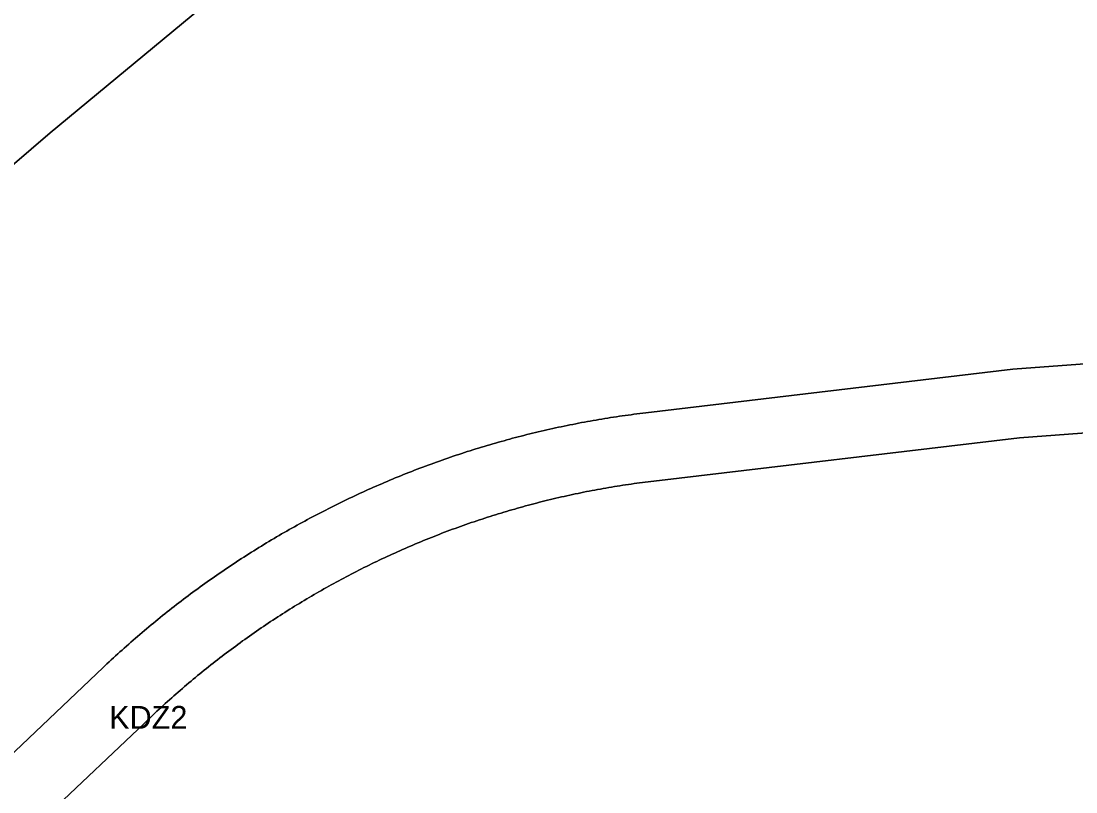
# Model space of a CAD drawing. Extents: x 7439486 to 7443435, y 5551288 to 5554556.
# Drawn here: x 7440134.7 to 7440595.5, y 5551897.3 to 5552233.9 of the extents above; entities that cross this region are included whole.
import ezdxf

# ---------------------------------------------------------------- set-up
doc = ezdxf.new("R2010")
doc.units = 0
doc.layers.add('linie_rozgraniczajace', color=7, linetype='Continuous')
doc.layers.add('oznaczenia_przeznaczen', color=7, linetype='Continuous')

msp = doc.modelspace()

# ---------------------------------------------------------------- linework, layer by layer
at = {"layer": 'linie_rozgraniczajace'}
for points in [[(7440130.74, 5552170.86), (7440147.39, 5552185.16), (7440180.28, 5552212.35), (7440213.17, 5552239.53)], [(7440213.17, 5552239.53), (7440180.28, 5552212.35), (7440147.39, 5552185.16), (7440130.74, 5552170.86)], [(7440349.37, 5552051.7), (7440350.61, 5552052.03), (7440351.86, 5552052.35), (7440353.11, 5552052.68), (7440354.35, 5552052.99), (7440355.6, 5552053.31), (7440356.85, 5552053.62), (7440358.1, 5552053.93), (7440359.36, 5552054.23), (7440360.61, 5552054.53), (7440361.86, 5552054.82), (7440363.12, 5552055.12), (7440364.38, 5552055.4), (7440365.63, 5552055.69), (7440366.89, 5552055.97), (7440368.15, 5552056.24), (7440369.41, 5552056.51), (7440370.67, 5552056.78), (7440371.93, 5552057.05), (7440373.19, 5552057.31), (7440374.45, 5552057.56), (7440375.72, 5552057.81), (7440376.98, 5552058.06), (7440378.24, 5552058.31), (7440379.51, 5552058.55), (7440380.78, 5552058.78), (7440382.04, 5552059.02), (7440383.31, 5552059.24), (7440384.58, 5552059.47), (7440385.85, 5552059.69), (7440387.12, 5552059.91), (7440388.39, 5552060.12), (7440389.66, 5552060.33), (7440390.93, 5552060.53), (7440392.21, 5552060.74), (7440393.48, 5552060.93), (7440394.75, 5552061.13), (7440396.03, 5552061.31), (7440397.3, 5552061.5), (7440398.58, 5552061.68), (7440399.85, 5552061.86), (7440401.13, 5552062.03), (7440402.41, 5552062.2), (7440403.69, 5552062.37), (7440404.96, 5552062.53), (7440406.24, 5552062.69), (7440407.52, 5552062.84), (7440567.97, 5552081.84), (7440667.99, 5552089.3)], [(7440667.99, 5552089.3), (7440567.97, 5552081.84), (7440407.52, 5552062.84), (7440406.24, 5552062.69), (7440404.96, 5552062.53), (7440403.69, 5552062.37), (7440402.41, 5552062.2), (7440401.13, 5552062.03), (7440399.85, 5552061.86), (7440398.58, 5552061.68), (7440397.3, 5552061.5), (7440396.03, 5552061.31), (7440394.75, 5552061.13), (7440393.48, 5552060.93), (7440392.21, 5552060.74), (7440390.93, 5552060.53), (7440389.66, 5552060.33), (7440388.39, 5552060.12), (7440387.12, 5552059.91), (7440385.85, 5552059.69), (7440384.58, 5552059.47), (7440383.31, 5552059.24), (7440382.04, 5552059.02), (7440380.78, 5552058.78), (7440379.51, 5552058.55), (7440378.24, 5552058.31), (7440376.98, 5552058.06), (7440375.72, 5552057.81), (7440374.45, 5552057.56), (7440373.19, 5552057.31), (7440371.93, 5552057.05), (7440370.67, 5552056.78), (7440369.41, 5552056.51), (7440368.15, 5552056.24), (7440366.89, 5552055.97), (7440365.63, 5552055.69), (7440364.38, 5552055.4), (7440363.12, 5552055.12), (7440361.86, 5552054.82), (7440360.61, 5552054.53), (7440359.36, 5552054.23), (7440358.1, 5552053.93), (7440356.85, 5552053.62)], [(7440670.22, 5552059.39), (7440570.85, 5552051.98), (7440411.05, 5552033.05), (7440409.82, 5552032.9), (7440408.59, 5552032.75), (7440407.35, 5552032.59), (7440406.12, 5552032.43), (7440404.89, 5552032.27), (7440403.66, 5552032.1), (7440402.44, 5552031.93), (7440401.21, 5552031.75), (7440399.98, 5552031.58), (7440398.75, 5552031.39), (7440397.53, 5552031.2), (7440396.3, 5552031.01), (7440395.07, 5552030.82), (7440393.85, 5552030.62), (7440392.63, 5552030.41), (7440391.4, 5552030.21), (7440390.18, 5552030), (7440388.96, 5552029.78), (7440387.74, 5552029.56), (7440386.52, 5552029.34), (7440385.29, 5552029.11), (7440384.08, 5552028.88), (7440382.86, 5552028.65), (7440381.64, 5552028.41), (7440380.42, 5552028.16), (7440379.21, 5552027.92), (7440377.99, 5552027.67), (7440376.78, 5552027.41), (7440375.56, 5552027.15), (7440374.35, 5552026.89), (7440373.14, 5552026.63), (7440371.93, 5552026.36), (7440370.72, 5552026.08), (7440369.51, 5552025.8), (7440368.3, 5552025.52), (7440367.09, 5552025.24), (7440365.89, 5552024.95), (7440364.68, 5552024.65), (7440363.48, 5552024.36), (7440362.27, 5552024.06), (7440361.07, 5552023.75), (7440359.87, 5552023.44), (7440358.67, 5552023.13), (7440357.47, 5552022.81), (7440356.27, 5552022.49), (7440355.07, 5552022.17), (7440353.87, 5552021.84), (7440352.68, 5552021.51), (7440351.48, 5552021.17), (7440350.29, 5552020.83), (7440349.1, 5552020.49), (7440347.91, 5552020.14), (7440346.72, 5552019.79), (7440345.53, 5552019.43), (7440344.34, 5552019.07), (7440343.15, 5552018.71), (7440341.97, 5552018.34), (7440340.78, 5552017.97), (7440339.6, 5552017.6), (7440338.42, 5552017.22), (7440337.24, 5552016.84), (7440336.06, 5552016.45), (7440334.88, 5552016.06), (7440333.7, 5552015.67), (7440332.53, 5552015.27)], [(7440352.68, 5552021.51), (7440353.87, 5552021.84), (7440355.07, 5552022.17), (7440356.27, 5552022.49), (7440357.47, 5552022.81), (7440358.67, 5552023.13), (7440359.87, 5552023.44), (7440361.07, 5552023.75), (7440362.27, 5552024.06), (7440363.48, 5552024.36), (7440364.68, 5552024.65), (7440365.89, 5552024.95), (7440367.09, 5552025.24), (7440368.3, 5552025.52), (7440369.51, 5552025.8), (7440370.72, 5552026.08), (7440371.93, 5552026.36), (7440373.14, 5552026.63), (7440374.35, 5552026.89), (7440375.56, 5552027.15), (7440376.78, 5552027.41), (7440377.99, 5552027.67), (7440379.21, 5552027.92), (7440380.42, 5552028.16), (7440381.64, 5552028.41), (7440382.86, 5552028.65), (7440384.08, 5552028.88), (7440385.29, 5552029.11), (7440386.52, 5552029.34), (7440387.74, 5552029.56), (7440388.96, 5552029.78), (7440390.18, 5552030), (7440391.4, 5552030.21), (7440392.63, 5552030.41), (7440393.85, 5552030.62), (7440395.07, 5552030.82), (7440396.3, 5552031.01), (7440397.53, 5552031.2), (7440398.75, 5552031.39), (7440399.98, 5552031.58), (7440401.21, 5552031.75), (7440402.44, 5552031.93), (7440403.66, 5552032.1), (7440404.89, 5552032.27), (7440406.12, 5552032.43), (7440407.35, 5552032.59), (7440408.59, 5552032.75), (7440409.82, 5552032.9), (7440411.05, 5552033.05), (7440570.85, 5552051.98), (7440670.22, 5552059.39)], [(7440356.85, 5552053.62), (7440355.6, 5552053.31), (7440354.35, 5552052.99), (7440353.11, 5552052.68), (7440351.86, 5552052.35), (7440350.61, 5552052.03), (7440349.37, 5552051.7), (7440348.12, 5552051.36), (7440346.88, 5552051.03), (7440345.64, 5552050.68), (7440344.4, 5552050.34), (7440343.16, 5552049.99), (7440341.92, 5552049.64), (7440340.68, 5552049.28), (7440339.44, 5552048.92), (7440338.21, 5552048.55), (7440336.97, 5552048.18), (7440335.74, 5552047.81), (7440334.51, 5552047.43), (7440333.28, 5552047.05), (7440332.05, 5552046.67), (7440330.82, 5552046.28), (7440329.59, 5552045.89), (7440328.36, 5552045.5), (7440327.14, 5552045.1), (7440325.92, 5552044.69), (7440324.69, 5552044.29), (7440323.47, 5552043.88), (7440322.25, 5552043.46), (7440321.03, 5552043.04), (7440319.82, 5552042.62), (7440318.6, 5552042.2), (7440317.39, 5552041.77), (7440316.17, 5552041.33), (7440314.96, 5552040.9), (7440313.75, 5552040.46), (7440312.54, 5552040.01), (7440311.33, 5552039.56), (7440310.13, 5552039.11), (7440308.92, 5552038.66), (7440307.72, 5552038.2), (7440306.52, 5552037.73), (7440305.32, 5552037.27), (7440304.12, 5552036.8), (7440302.92, 5552036.32), (7440301.72, 5552035.84), (7440300.53, 5552035.36), (7440299.33, 5552034.88), (7440298.14, 5552034.39), (7440296.95, 5552033.89), (7440295.76, 5552033.4), (7440294.58, 5552032.9), (7440293.39, 5552032.39), (7440292.21, 5552031.88), (7440291.02, 5552031.37), (7440289.84, 5552030.86), (7440288.66, 5552030.34), (7440287.49, 5552029.82), (7440286.31, 5552029.29), (7440285.14, 5552028.76), (7440283.96, 5552028.23), (7440282.79, 5552027.69), (7440281.62, 5552027.15), (7440280.45, 5552026.61), (7440279.29, 5552026.06), (7440278.12, 5552025.51), (7440276.96, 5552024.95), (7440275.8, 5552024.39), (7440274.64, 5552023.83), (7440273.49, 5552023.27), (7440272.33, 5552022.7), (7440271.18, 5552022.12), (7440270.02, 5552021.55), (7440268.87, 5552020.97), (7440267.72, 5552020.38), (7440266.58, 5552019.8), (7440265.43, 5552019.2), (7440264.29, 5552018.61), (7440263.15, 5552018.01), (7440262.01, 5552017.41), (7440260.87, 5552016.8), (7440259.74, 5552016.2), (7440258.6, 5552015.59), (7440257.47, 5552014.97), (7440256.34, 5552014.35), (7440255.21, 5552013.73), (7440254.09, 5552013.1), (7440252.96, 5552012.47), (7440251.84, 5552011.84), (7440250.72, 5552011.2), (7440249.6, 5552010.56), (7440248.49, 5552009.92), (7440247.37, 5552009.27), (7440246.26, 5552008.62), (7440245.15, 5552007.97), (7440244.04, 5552007.31), (7440242.94, 5552006.65), (7440241.83, 5552005.99), (7440240.73, 5552005.32), (7440239.63, 5552004.65)], [(7440233.08, 5552000.55), (7440234.17, 5552001.24), (7440235.25, 5552001.93), (7440236.35, 5552002.61), (7440237.44, 5552003.29), (7440238.53, 5552003.97), (7440239.63, 5552004.65), (7440240.73, 5552005.32), (7440241.83, 5552005.99), (7440242.94, 5552006.65), (7440244.04, 5552007.31), (7440245.15, 5552007.97), (7440246.26, 5552008.62), (7440247.37, 5552009.27), (7440248.49, 5552009.92), (7440249.6, 5552010.56), (7440250.72, 5552011.2), (7440251.84, 5552011.84), (7440252.96, 5552012.47), (7440254.09, 5552013.1), (7440255.21, 5552013.73), (7440256.34, 5552014.35), (7440257.47, 5552014.97), (7440258.6, 5552015.59), (7440259.74, 5552016.2), (7440260.87, 5552016.8), (7440262.01, 5552017.41), (7440263.15, 5552018.01), (7440264.29, 5552018.61), (7440265.43, 5552019.2), (7440266.58, 5552019.8), (7440267.72, 5552020.38), (7440268.87, 5552020.97), (7440270.02, 5552021.55), (7440271.18, 5552022.12), (7440272.33, 5552022.7), (7440273.49, 5552023.27), (7440274.64, 5552023.83), (7440275.8, 5552024.39), (7440276.96, 5552024.95), (7440278.12, 5552025.51), (7440279.29, 5552026.06), (7440280.45, 5552026.61), (7440281.62, 5552027.15), (7440282.79, 5552027.69), (7440283.96, 5552028.23), (7440285.14, 5552028.76), (7440286.31, 5552029.29), (7440287.49, 5552029.82), (7440288.66, 5552030.34), (7440289.84, 5552030.86), (7440291.02, 5552031.37), (7440292.21, 5552031.88), (7440293.39, 5552032.39), (7440294.58, 5552032.9), (7440295.76, 5552033.4), (7440296.95, 5552033.89), (7440298.14, 5552034.39), (7440299.33, 5552034.88), (7440300.53, 5552035.36), (7440301.72, 5552035.84), (7440302.92, 5552036.32), (7440304.12, 5552036.8), (7440305.32, 5552037.27), (7440306.52, 5552037.73), (7440307.72, 5552038.2), (7440308.92, 5552038.66), (7440310.13, 5552039.11), (7440311.33, 5552039.56), (7440312.54, 5552040.01), (7440313.75, 5552040.46), (7440314.96, 5552040.9), (7440316.17, 5552041.33), (7440317.39, 5552041.77), (7440318.6, 5552042.2), (7440319.82, 5552042.62), (7440321.03, 5552043.04), (7440322.25, 5552043.46), (7440323.47, 5552043.88), (7440324.69, 5552044.29), (7440325.92, 5552044.69), (7440327.14, 5552045.1), (7440328.36, 5552045.5), (7440329.59, 5552045.89), (7440330.82, 5552046.28), (7440332.05, 5552046.67), (7440333.28, 5552047.05), (7440334.51, 5552047.43), (7440335.74, 5552047.81), (7440336.97, 5552048.18), (7440338.21, 5552048.55), (7440339.44, 5552048.92), (7440340.68, 5552049.28), (7440341.92, 5552049.64), (7440343.16, 5552049.99), (7440344.4, 5552050.34), (7440345.64, 5552050.68), (7440346.88, 5552051.03), (7440348.12, 5552051.36), (7440349.37, 5552051.7)], [(7440241.6, 5551970.27), (7440242.63, 5551970.96), (7440243.66, 5551971.65), (7440244.7, 5551972.33), (7440245.74, 5551973.01), (7440246.78, 5551973.69), (7440247.82, 5551974.37), (7440248.86, 5551975.04), (7440249.91, 5551975.7), (7440250.96, 5551976.37), (7440252.01, 5551977.03), (7440253.06, 5551977.68), (7440254.12, 5551978.34), (7440255.17, 5551978.99), (7440256.23, 5551979.63), (7440257.29, 5551980.28), (7440258.35, 5551980.92), (7440259.42, 5551981.55), (7440260.49, 5551982.19), (7440261.56, 5551982.82), (7440262.63, 5551983.44), (7440263.7, 5551984.06), (7440264.78, 5551984.68), (7440265.85, 5551985.3), (7440266.93, 5551985.91), (7440268.01, 5551986.52), (7440269.1, 5551987.13), (7440270.18, 5551987.73), (7440271.27, 5551988.33), (7440272.36, 5551988.92), (7440273.45, 5551989.51), (7440274.54, 5551990.1), (7440275.64, 5551990.68), (7440276.74, 5551991.26), (7440277.83, 5551991.84), (7440278.93, 5551992.41), (7440280.04, 5551992.98), (7440281.14, 5551993.55), (7440282.25, 5551994.11), (7440283.35, 5551994.67), (7440284.46, 5551995.23), (7440285.57, 5551995.78), (7440286.69, 5551996.33), (7440287.8, 5551996.87), (7440288.92, 5551997.42), (7440290.04, 5551997.95), (7440291.16, 5551998.49), (7440292.28, 5551999.02), (7440293.4, 5551999.54), (7440294.53, 5552000.07), (7440295.65, 5552000.59), (7440296.78, 5552001.1), (7440297.91, 5552001.62), (7440299.04, 5552002.13), (7440300.18, 5552002.63), (7440301.31, 5552003.13), (7440302.45, 5552003.63), (7440303.59, 5552004.12), (7440304.73, 5552004.61), (7440305.87, 5552005.1), (7440307.01, 5552005.59), (7440308.16, 5552006.06), (7440309.3, 5552006.54), (7440310.45, 5552007.01), (7440311.6, 5552007.48), (7440312.75, 5552007.94), (7440313.9, 5552008.41), (7440315.05, 5552008.86), (7440316.21, 5552009.32), (7440317.37, 5552009.77), (7440318.52, 5552010.21), (7440319.68, 5552010.65), (7440320.84, 5552011.09), (7440322.01, 5552011.53), (7440323.17, 5552011.96), (7440324.33, 5552012.39), (7440325.5, 5552012.81), (7440326.67, 5552013.23), (7440327.84, 5552013.65), (7440329.01, 5552014.06), (7440330.18, 5552014.47), (7440331.35, 5552014.87), (7440332.53, 5552015.27), (7440333.7, 5552015.67), (7440334.88, 5552016.06), (7440336.06, 5552016.45), (7440337.24, 5552016.84), (7440338.42, 5552017.22), (7440339.6, 5552017.6), (7440340.78, 5552017.97), (7440341.97, 5552018.34), (7440343.15, 5552018.71), (7440344.34, 5552019.07), (7440345.53, 5552019.43), (7440346.72, 5552019.79), (7440347.91, 5552020.14), (7440349.1, 5552020.49), (7440350.29, 5552020.83), (7440351.48, 5552021.17), (7440352.68, 5552021.51)], [(7440332.53, 5552015.27), (7440331.35, 5552014.87), (7440330.18, 5552014.47), (7440329.01, 5552014.06), (7440327.84, 5552013.65), (7440326.67, 5552013.23), (7440325.5, 5552012.81), (7440324.33, 5552012.39), (7440323.17, 5552011.96), (7440322.01, 5552011.53), (7440320.84, 5552011.09), (7440319.68, 5552010.65), (7440318.52, 5552010.21), (7440317.37, 5552009.77), (7440316.21, 5552009.32), (7440315.05, 5552008.86), (7440313.9, 5552008.41), (7440312.75, 5552007.94), (7440311.6, 5552007.48), (7440310.45, 5552007.01), (7440309.3, 5552006.54), (7440308.16, 5552006.06), (7440307.01, 5552005.59), (7440305.87, 5552005.1), (7440304.73, 5552004.61), (7440303.59, 5552004.12), (7440302.45, 5552003.63), (7440301.31, 5552003.13), (7440300.18, 5552002.63), (7440299.04, 5552002.13), (7440297.91, 5552001.62), (7440296.78, 5552001.1), (7440295.65, 5552000.59), (7440294.53, 5552000.07), (7440293.4, 5551999.54), (7440292.28, 5551999.02), (7440291.16, 5551998.49), (7440290.04, 5551997.95), (7440288.92, 5551997.42), (7440287.8, 5551996.87), (7440286.69, 5551996.33), (7440285.57, 5551995.78), (7440284.46, 5551995.23), (7440283.35, 5551994.67), (7440282.25, 5551994.11), (7440281.14, 5551993.55), (7440280.04, 5551992.98), (7440278.93, 5551992.41), (7440277.83, 5551991.84), (7440276.74, 5551991.26), (7440275.64, 5551990.68), (7440274.54, 5551990.1), (7440273.45, 5551989.51), (7440272.36, 5551988.92), (7440271.27, 5551988.33), (7440270.18, 5551987.73), (7440269.1, 5551987.13), (7440268.01, 5551986.52), (7440266.93, 5551985.91), (7440265.85, 5551985.3), (7440264.78, 5551984.68), (7440263.7, 5551984.06), (7440262.63, 5551983.44), (7440261.56, 5551982.82), (7440260.49, 5551982.19), (7440259.42, 5551981.55), (7440258.35, 5551980.92), (7440257.29, 5551980.28), (7440256.23, 5551979.63), (7440255.17, 5551978.99), (7440254.12, 5551978.34), (7440253.06, 5551977.68), (7440252.01, 5551977.03), (7440250.96, 5551976.37), (7440249.91, 5551975.7), (7440248.86, 5551975.04), (7440247.82, 5551974.37), (7440246.78, 5551973.69), (7440245.74, 5551973.01), (7440244.7, 5551972.33), (7440243.66, 5551971.65), (7440242.63, 5551970.96), (7440241.6, 5551970.27), (7440240.57, 5551969.58), (7440239.54, 5551968.88), (7440238.52, 5551968.18), (7440237.5, 5551967.48), (7440236.48, 5551966.77), (7440235.46, 5551966.06), (7440234.44, 5551965.35), (7440233.43, 5551964.63), (7440232.42, 5551963.91), (7440231.41, 5551963.19), (7440230.41, 5551962.46), (7440229.4, 5551961.73), (7440228.4, 5551961), (7440227.4, 5551960.26), (7440226.41, 5551959.52), (7440225.41, 5551958.78), (7440224.42, 5551958.03)], [(7440239.63, 5552004.65), (7440238.53, 5552003.97), (7440237.44, 5552003.29), (7440236.35, 5552002.61), (7440235.25, 5552001.93), (7440234.17, 5552001.24), (7440233.08, 5552000.55), (7440231.99, 5551999.85), (7440230.91, 5551999.16), (7440229.83, 5551998.45), (7440228.75, 5551997.75), (7440227.68, 5551997.04), (7440226.6, 5551996.33), (7440225.53, 5551995.61), (7440224.46, 5551994.9), (7440223.39, 5551994.17), (7440222.33, 5551993.45), (7440221.26, 5551992.72), (7440220.2, 5551991.99), (7440219.15, 5551991.26), (7440218.09, 5551990.52), (7440217.04, 5551989.78), (7440215.99, 5551989.03), (7440214.94, 5551988.28), (7440213.89, 5551987.53), (7440212.84, 5551986.78), (7440211.8, 5551986.02), (7440210.76, 5551985.26), (7440209.73, 5551984.5), (7440208.69, 5551983.73), (7440207.66, 5551982.96), (7440206.63, 5551982.19), (7440205.6, 5551981.41), (7440204.57, 5551980.63), (7440203.55, 5551979.85), (7440202.53, 5551979.06), (7440201.51, 5551978.27), (7440200.5, 5551977.48), (7440199.49, 5551976.68), (7440198.47, 5551975.88), (7440197.47, 5551975.08), (7440196.46, 5551974.27), (7440195.46, 5551973.47), (7440194.46, 5551972.65), (7440193.46, 5551971.84), (7440192.46, 5551971.02), (7440191.47, 5551970.2), (7440190.48, 5551969.38), (7440189.49, 5551968.55), (7440188.51, 5551967.72), (7440187.52, 5551966.89), (7440186.54, 5551966.05), (7440185.57, 5551965.21), (7440184.59, 5551964.37), (7440183.62, 5551963.53), (7440182.65, 5551962.68), (7440181.68, 5551961.83), (7440180.72, 5551960.97), (7440179.76, 5551960.12), (7440178.8, 5551959.25), (7440177.84, 5551958.39), (7440176.89, 5551957.53), (7440175.94, 5551956.66), (7440174.99, 5551955.78), (7440174.04, 5551954.91), (7440173.1, 5551954.03), (7440172.16, 5551953.15), (7440171.22, 5551952.27), (7440170.49, 5551951.58), (7439741.39, 5551543.86)], [(7439741.39, 5551543.86), (7440170.49, 5551951.58), (7440171.22, 5551952.27), (7440172.16, 5551953.15), (7440173.1, 5551954.03), (7440174.04, 5551954.91), (7440174.99, 5551955.78), (7440175.94, 5551956.66), (7440176.89, 5551957.53), (7440177.84, 5551958.39), (7440178.8, 5551959.25), (7440179.76, 5551960.12), (7440180.72, 5551960.97), (7440181.68, 5551961.83), (7440182.65, 5551962.68), (7440183.62, 5551963.53), (7440184.59, 5551964.37), (7440185.57, 5551965.21), (7440186.54, 5551966.05), (7440187.52, 5551966.89), (7440188.51, 5551967.72), (7440189.49, 5551968.55), (7440190.48, 5551969.38), (7440191.47, 5551970.2), (7440192.46, 5551971.02), (7440193.46, 5551971.84), (7440194.46, 5551972.65), (7440195.46, 5551973.47), (7440196.46, 5551974.27), (7440197.47, 5551975.08), (7440198.47, 5551975.88), (7440199.49, 5551976.68), (7440200.5, 5551977.48), (7440201.51, 5551978.27), (7440202.53, 5551979.06), (7440203.55, 5551979.85), (7440204.57, 5551980.63), (7440205.6, 5551981.41), (7440206.63, 5551982.19), (7440207.66, 5551982.96), (7440208.69, 5551983.73), (7440209.73, 5551984.5), (7440210.76, 5551985.26), (7440211.8, 5551986.02), (7440212.84, 5551986.78), (7440213.89, 5551987.53), (7440214.94, 5551988.28), (7440215.99, 5551989.03), (7440217.04, 5551989.78), (7440218.09, 5551990.52), (7440219.15, 5551991.26), (7440220.2, 5551991.99), (7440221.26, 5551992.72), (7440222.33, 5551993.45), (7440223.39, 5551994.17), (7440224.46, 5551994.9), (7440225.53, 5551995.61), (7440226.6, 5551996.33), (7440227.68, 5551997.04), (7440228.75, 5551997.75), (7440229.83, 5551998.45), (7440230.91, 5551999.16), (7440231.99, 5551999.85), (7440233.08, 5552000.55)], [(7440145.09, 5551886.05), (7440191.16, 5551929.83), (7440191.3, 5551929.97), (7440192.2, 5551930.82), (7440193.11, 5551931.67), (7440194.02, 5551932.52), (7440194.92, 5551933.37), (7440195.84, 5551934.21), (7440196.75, 5551935.04), (7440197.67, 5551935.88), (7440198.59, 5551936.71), (7440199.51, 5551937.54), (7440200.44, 5551938.37), (7440201.37, 5551939.19), (7440202.3, 5551940.01), (7440203.23, 5551940.83), (7440204.17, 5551941.64), (7440205.11, 5551942.45), (7440206.05, 5551943.26), (7440206.99, 5551944.07), (7440207.94, 5551944.87), (7440208.89, 5551945.67), (7440209.84, 5551946.46), (7440210.8, 5551947.26), (7440211.75, 5551948.05), (7440212.71, 5551948.83), (7440213.67, 5551949.62), (7440214.64, 5551950.4), (7440215.61, 5551951.18), (7440216.58, 5551951.95), (7440217.55, 5551952.72), (7440218.52, 5551953.49), (7440219.5, 5551954.26), (7440220.48, 5551955.02), (7440221.46, 5551955.77), (7440222.45, 5551956.53), (7440223.43, 5551957.28), (7440224.42, 5551958.03), (7440225.41, 5551958.78), (7440226.41, 5551959.52), (7440227.4, 5551960.26), (7440228.4, 5551961), (7440229.4, 5551961.73), (7440230.41, 5551962.46), (7440231.41, 5551963.19), (7440232.42, 5551963.91), (7440233.43, 5551964.63), (7440234.44, 5551965.35), (7440235.46, 5551966.06), (7440236.48, 5551966.77), (7440237.5, 5551967.48), (7440238.52, 5551968.18), (7440239.54, 5551968.88), (7440240.57, 5551969.58), (7440241.6, 5551970.27)], [(7440224.42, 5551958.03), (7440223.43, 5551957.28), (7440222.45, 5551956.53), (7440221.46, 5551955.77), (7440220.48, 5551955.02), (7440219.5, 5551954.26), (7440218.52, 5551953.49), (7440217.55, 5551952.72), (7440216.58, 5551951.95), (7440215.61, 5551951.18), (7440214.64, 5551950.4), (7440213.67, 5551949.62), (7440212.71, 5551948.83), (7440211.75, 5551948.05), (7440210.8, 5551947.26), (7440209.84, 5551946.46), (7440208.89, 5551945.67), (7440207.94, 5551944.87), (7440206.99, 5551944.07), (7440206.05, 5551943.26), (7440205.11, 5551942.45), (7440204.17, 5551941.64), (7440203.23, 5551940.83), (7440202.3, 5551940.01), (7440201.37, 5551939.19), (7440200.44, 5551938.37), (7440199.51, 5551937.54), (7440198.59, 5551936.71), (7440197.67, 5551935.88), (7440196.75, 5551935.04), (7440195.84, 5551934.21), (7440194.92, 5551933.37), (7440194.02, 5551932.52), (7440193.11, 5551931.67), (7440192.2, 5551930.82), (7440191.3, 5551929.97), (7440191.16, 5551929.83), (7440145.09, 5551886.05)]]:
    msp.add_lwpolyline(points, dxfattribs=at)

# ---------------------------------------------------------------- texts
at = {"layer": 'oznaczenia_przeznaczen'}
msp.add_text('KDZ2', height=10, dxfattribs=at).set_placement((7440173.13, 5551924.83))

doc.saveas('drawing.dxf')
